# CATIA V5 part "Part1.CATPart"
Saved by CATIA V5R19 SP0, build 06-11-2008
Part number: Part1
Publications: "Face"
Bounding box of the stored display mesh (mm): x -53.402 to 71.586, y -25.205 to 55.128, z 0 to 30
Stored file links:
  C:\Documents and Settings\Jan Svoboda\Plocha\CATIA-help\Test_public\Part1.CATPart
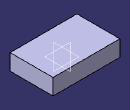
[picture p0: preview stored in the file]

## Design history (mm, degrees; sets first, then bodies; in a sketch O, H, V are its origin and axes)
Body1 (main body)
  Sketch1 on xy-plane, origin (0, 0, 0), H (1, 0, 0), V (0, 1, 0)
    line L1 (-53.402, 55.1283) -> (71.5863, 55.1283)
    line L2 (71.5863, 55.1283) -> (71.5863, -25.2048)
    line L3 (71.5863, -25.2048) -> (-53.402, -25.2048)
    line L4 (-53.402, -25.2048) -> (-53.402, 55.1283)
  Pad1: profile Sketch1, direction (0, 0, 1), length 30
